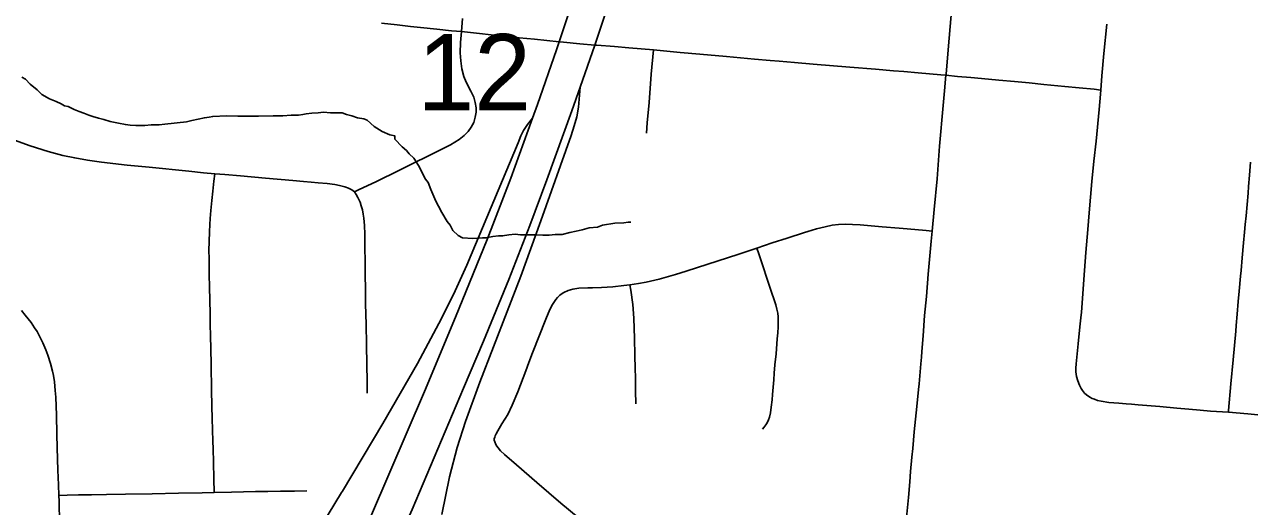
# Model space of a CAD drawing. Extents: x 0 to 34, y 0 to 22.
# Drawn here: x 3.895 to 4.566, y 15.8 to 16.064 of the extents above; entities that cross this region are included whole.
import ezdxf

# ---------------------------------------------------------------- set-up
doc = ezdxf.new("R2010")
doc.units = 0
for name, color, linetype in [('GM_X_City_Street', 7, 'Continuous'), ('GM_X_Interchange_Ramps', 7, 'Continuous'), ('GM_X_Interstate_Route', 7, 'Continuous'), ('GM_X_Minor_River', 7, 'Continuous'), ('GM_X_Section_Text', 7, 'Continuous')]:
    doc.layers.add(name, color=color, linetype=linetype)

msp = doc.modelspace()

# ---------------------------------------------------------------- linework, layer by layer
at = {"layer": 'GM_X_City_Street'}
for points in [[(4.37821, 15.79422), (4.37887, 15.80158), (4.37925, 15.80522), (4.37997, 15.81377), (4.3804, 15.81948), (4.38112, 15.82726), (4.38154, 15.83215), (4.38229, 15.84127), (4.38376, 15.85511), (4.38476, 15.86441), (4.38503, 15.86745), (4.38596, 15.87848), (4.38628, 15.88214), (4.38652, 15.88517), (4.38721, 15.89379), (4.38805, 15.90493), (4.38908, 15.91542), (4.39009, 15.92753), (4.39118, 15.93957), (4.39169, 15.94576), (4.39219, 15.95124), (4.39327, 15.96304), (4.39486, 15.97977), (4.39628, 15.99774), (4.39829, 16.01999), (4.399, 16.02798), (4.39973, 16.0366), (4.39978, 16.03725), (4.40112, 16.05272), (4.40372, 16.08242)], [(4.1351, 16.06761), (4.13448, 16.06049), (4.13398, 16.0546), (4.13376, 16.04894), (4.13402, 16.04452), (4.13469, 16.04013), (4.13581, 16.03581), (4.13699, 16.03282), (4.13962, 16.02785), (4.14114, 16.02457), (4.14198, 16.02173), (4.14243, 16.01881), (4.14246, 16.01645), (4.14204, 16.01353), (4.14116, 16.01072), (4.13983, 16.00809), (4.13809, 16.00571), (4.13598, 16.00361), (4.13312, 16.0014), (4.12842, 15.99855), (4.11575, 15.99204), (4.10849, 15.98855), (4.10015, 15.98439), (4.08791, 15.97837), (4.07813, 15.97374), (4.07581, 15.97263)], [(4.09061, 16.06506), (4.09933, 16.06412), (4.10659, 16.06329), (4.11203, 16.06269), (4.12091, 16.06175), (4.12908, 16.06092), (4.13448, 16.06049), (4.14104, 16.05974), (4.15401, 16.05841), (4.16601, 16.05716), (4.17438, 16.05631), (4.18798, 16.05489), (4.19027, 16.05466), (4.19919, 16.05379), (4.2074, 16.05313), (4.20866, 16.05303), (4.21834, 16.05227), (4.22606, 16.05161), (4.23955, 16.05042), (4.25413, 16.04912), (4.2649, 16.04813), (4.27959, 16.04683), (4.29492, 16.04541), (4.30341, 16.04465), (4.30841, 16.04422), (4.31679, 16.04357), (4.32712, 16.0427), (4.34714, 16.04095), (4.36117, 16.03986), (4.37107, 16.03899), (4.37673, 16.03856), (4.38456, 16.03789), (4.39686, 16.03684), (4.39973, 16.0366), (4.40599, 16.03595), (4.41328, 16.0353), (4.41915, 16.03476), (4.42873, 16.03389), (4.43722, 16.03312), (4.44537, 16.03236), (4.45342, 16.0316), (4.46484, 16.03051), (4.47268, 16.02975), (4.48094, 16.02888), (4.48455, 16.0285)], [(4.47976, 15.85954), (4.47847, 15.86023), (4.47678, 15.86142), (4.4757, 15.86241), (4.4745, 15.8639), (4.47381, 15.86504), (4.47287, 15.86675), (4.47191, 15.86912), (4.47125, 15.87157), (4.47092, 15.87408), (4.47082, 15.87617), (4.47101, 15.87845), (4.47137, 15.8821), (4.47217, 15.88949), (4.47309, 15.89872), (4.47357, 15.90365), (4.47388, 15.90673), (4.47434, 15.91164), (4.47527, 15.92462), (4.47639, 15.93956), (4.47748, 15.95216), (4.47818, 15.96118), (4.47966, 15.97844), (4.48075, 15.98954), (4.48194, 16.00044), (4.48364, 16.01782), (4.48405, 16.02199), (4.48455, 16.0285), (4.48514, 16.03618), (4.48615, 16.04856), (4.48779, 16.06451)], [(4.23569, 16.00489), (4.23622, 16.0105), (4.23715, 16.02173), (4.23825, 16.03725), (4.23955, 16.05042)], [(3.88778, 16.0018), (3.89824, 15.99792), (3.90806, 15.99478), (3.91613, 15.99265), (3.92269, 15.99128), (3.92971, 15.99006), (3.93743, 15.98891), (3.95149, 15.98737), (3.96341, 15.98625), (3.98514, 15.98401), (3.99315, 15.98315), (3.99944, 15.9826), (4.00487, 15.98212), (4.01352, 15.98141), (4.02707, 15.98024), (4.04204, 15.97888), (4.04795, 15.97837), (4.05207, 15.97803), (4.05604, 15.97769), (4.061, 15.9772), (4.06505, 15.97665), (4.06776, 15.97614), (4.0705, 15.97545), (4.07256, 15.97476), (4.07445, 15.97374), (4.07581, 15.97263), (4.07685, 15.97133), (4.07779, 15.96962), (4.07891, 15.96713), (4.07959, 15.96499), (4.08019, 15.96285), (4.0807, 15.96053), (4.08105, 15.95822), (4.08138, 15.95428), (4.08156, 15.94947), (4.08156, 15.94235), (4.08165, 15.93438), (4.08174, 15.92658), (4.08182, 15.92006), (4.08199, 15.9114), (4.08229, 15.89997), (4.08244, 15.889), (4.0826, 15.87802), (4.08275, 15.86902), (4.08275, 15.86247)], [(4.55447, 15.85197), (4.55454, 15.85288), (4.55579, 15.86755), (4.55701, 15.88067), (4.55767, 15.88844), (4.55842, 15.89641), (4.55865, 15.8995), (4.55918, 15.90564), (4.55979, 15.91272), (4.5603, 15.91831), (4.5611, 15.92653), (4.56143, 15.92958), (4.56199, 15.93662), (4.56276, 15.94476), (4.56327, 15.9507), (4.56366, 15.95473), (4.56407, 15.95965), (4.56517, 15.97197), (4.56542, 15.97564), (4.56589, 15.9818), (4.56657, 15.98901)], [(3.99904, 15.80802), (3.99893, 15.81551), (3.9987, 15.82457), (3.99848, 15.83184), (3.99837, 15.83609), (3.99803, 15.84849), (3.99781, 15.85521), (3.99761, 15.8643), (3.99736, 15.87779), (3.99714, 15.88707), (3.99701, 15.89344), (3.99684, 15.90042), (3.9968, 15.90641), (3.99669, 15.91289), (3.99647, 15.92106), (3.99638, 15.92689), (3.99633, 15.93129), (3.99624, 15.93616), (3.9962, 15.94049), (3.99624, 15.94543), (3.99647, 15.9508), (3.99669, 15.95482), (3.99691, 15.95817), (3.99725, 15.96253), (3.99781, 15.9679), (3.9983, 15.97313), (3.99891, 15.97862), (3.99944, 15.9826)], [(4.15237, 15.83663), (4.15245, 15.83747), (4.15267, 15.83835), (4.15291, 15.83911), (4.15338, 15.84016), (4.15433, 15.84176), (4.15662, 15.84552), (4.15977, 15.8508), (4.16217, 15.85576), (4.16525, 15.86309), (4.16963, 15.87464), (4.17136, 15.87928), (4.17333, 15.8845), (4.1806, 15.90303), (4.18283, 15.90821), (4.18428, 15.91106), (4.18609, 15.91374), (4.18708, 15.91483), (4.18839, 15.91605), (4.18959, 15.91693), (4.19057, 15.91753), (4.19295, 15.91866), (4.19545, 15.91945), (4.19864, 15.91995), (4.20369, 15.92016), (4.20616, 15.9202), (4.21112, 15.92031), (4.21727, 15.92061), (4.2234, 15.92135), (4.22671, 15.92185), (4.23133, 15.92256), (4.23556, 15.9233), (4.23795, 15.9238), (4.24273, 15.9249), (4.25172, 15.92742), (4.25742, 15.92933), (4.28637, 15.93864), (4.29618, 15.94191), (4.30462, 15.94473), (4.31289, 15.9474), (4.32232, 15.95041), (4.32408, 15.95096), (4.32881, 15.95238), (4.33365, 15.95359), (4.33738, 15.95438), (4.34096, 15.9548), (4.34455, 15.95495), (4.34849, 15.95488), (4.35286, 15.95459), (4.36479, 15.9536), (4.37408, 15.9528), (4.37845, 15.95237), (4.38892, 15.95151), (4.39219, 15.95124)], [(4.29926, 15.84275), (4.30009, 15.84367), (4.3012, 15.84513), (4.30186, 15.84616), (4.30264, 15.84782), (4.30319, 15.84922), (4.30369, 15.85159), (4.30412, 15.85474), (4.30455, 15.85868), (4.30476, 15.86177), (4.30541, 15.86979), (4.3057, 15.87331), (4.30612, 15.87797), (4.3067, 15.88391), (4.30739, 15.89219), (4.3077, 15.89545), (4.30785, 15.89883), (4.30792, 15.90155), (4.30793, 15.90428), (4.30767, 15.90625), (4.30713, 15.90836), (4.30652, 15.91084), (4.30548, 15.91402), (4.30442, 15.91715), (4.30182, 15.92484), (4.29953, 15.93216), (4.29724, 15.93882), (4.29618, 15.94191)], [(4.22993, 15.85648), (4.2299, 15.8577), (4.22983, 15.86266), (4.22975, 15.86661), (4.22967, 15.87098), (4.2295, 15.87577), (4.22941, 15.88316), (4.2292, 15.89234), (4.22883, 15.90352), (4.22827, 15.91095), (4.22714, 15.9189), (4.22671, 15.92185)], [(3.89351, 15.90761), (3.89562, 15.90511), (3.89726, 15.90311), (3.8988, 15.90106), (3.90074, 15.89828), (3.90205, 15.89617), (3.90347, 15.89361), (3.90524, 15.88991), (3.90683, 15.88615), (3.90791, 15.8833), (3.90945, 15.87864), (3.91053, 15.87454), (3.91104, 15.87209), (3.91155, 15.86868), (3.91183, 15.86629), (3.91206, 15.86378), (3.91229, 15.86019), (3.91263, 15.85035), (3.91297, 15.83993), (3.91309, 15.83242), (3.91349, 15.8203), (3.91383, 15.81216), (3.91405, 15.8063), (3.91417, 15.80322), (3.91439, 15.79127)], [(4.47976, 15.85954), (4.48115, 15.85904), (4.48274, 15.85847), (4.48465, 15.85803), (4.48898, 15.85736), (4.49444, 15.85686), (4.49835, 15.85661), (4.5014, 15.85634), (4.50507, 15.85606), (4.51695, 15.85507), (4.52608, 15.85418), (4.53281, 15.85359), (4.53893, 15.85303), (4.5446, 15.85258), (4.55447, 15.85197), (4.56497, 15.85109), (4.57052, 15.85062)], [(4.15237, 15.83663), (4.15271, 15.83571), (4.15329, 15.83428), (4.15384, 15.83332), (4.15447, 15.83244), (4.15586, 15.83078), (4.15797, 15.82887), (4.16452, 15.82317), (4.17578, 15.81348), (4.18886, 15.80208), (4.1983, 15.79435)], [(3.91405, 15.8063), (3.91854, 15.80646), (3.9248, 15.80668), (3.93195, 15.80679), (3.94008, 15.80692), (3.95051, 15.80702), (3.96516, 15.80724), (3.97958, 15.80758), (3.99244, 15.8078), (3.99904, 15.80802), (4.00854, 15.80825), (4.02173, 15.80847), (4.02844, 15.80858), (4.03538, 15.8087), (4.04309, 15.80881), (4.0498, 15.80892)]]:
    msp.add_lwpolyline(points, dxfattribs=at)
at = {"layer": 'GM_X_Interchange_Ramps'}
for points in [[(4.12365, 15.79586), (4.12798, 15.81651), (4.13218, 15.83273), (4.13665, 15.84694), (4.14452, 15.86852), (4.16688, 15.92645), (4.17788, 15.9568), (4.19454, 16.00366), (4.19611, 16.00889), (4.19756, 16.01381), (4.19857, 16.01902), (4.19942, 16.03008)], [(4.17334, 16.01314), (4.17055, 16.00965), (4.16847, 16.00629), (4.16702, 16.00339), (4.16556, 15.99963), (4.13747, 15.93253), (4.13104, 15.91839), (4.12355, 15.90336), (4.11034, 15.8787), (4.09145, 15.84581), (4.06926, 15.80881)], [(4.06926, 15.80881), (4.06875, 15.80795), (4.05358, 15.78298), (4.0351, 15.75205), (4.01147, 15.71046), (4.00147, 15.69185), (3.98862, 15.66693), (3.98806, 15.66545), (3.98659, 15.66157), (3.98573, 15.65749)]]:
    msp.add_lwpolyline(points, dxfattribs=at)
at = {"layer": 'GM_X_Interstate_Route'}
for points in [[(4.04209, 15.6451), (4.04357, 15.64893), (4.04429, 15.65077), (4.04711, 15.65808), (4.05031, 15.66635), (4.0632, 15.69737), (4.08832, 15.7549), (4.09895, 15.77929), (4.10742, 15.79874), (4.13553, 15.86511), (4.14651, 15.89081), (4.16048, 15.92466), (4.17191, 15.95418), (4.18122, 15.9792), (4.19495, 16.01715), (4.19942, 16.03008), (4.2074, 16.05313), (4.21119, 16.0641), (4.21847, 16.08652)], [(3.93014, 15.35354), (3.94101, 15.39627), (3.95006, 15.42983), (3.95887, 15.46023), (3.97267, 15.50405), (3.98526, 15.54173), (4.00587, 15.59967), (4.02014, 15.63941), (4.02545, 15.65322), (4.0282, 15.66039), (4.0326, 15.67184), (4.04557, 15.70341), (4.05882, 15.73421), (4.07579, 15.7736), (4.1142, 15.86326), (4.13123, 15.90398), (4.1485, 15.94663), (4.16145, 15.98029), (4.17334, 16.01314), (4.17605, 16.02063), (4.18654, 16.05056), (4.18798, 16.05489), (4.19729, 16.08303)]]:
    msp.add_lwpolyline(points, dxfattribs=at)
at = {"layer": 'GM_X_Minor_River'}
for points in [[(3.89377, 16.03561), (3.89565, 16.03445), (3.89828, 16.03176), (3.90205, 16.02868), (3.90468, 16.026), (3.90883, 16.02367), (3.91261, 16.02212), (3.91525, 16.02095), (3.91714, 16.01979), (3.91903, 16.01939), (3.92243, 16.01783), (3.92508, 16.01667), (3.92773, 16.01588), (3.93037, 16.01471), (3.93264, 16.01393), (3.93567, 16.01314), (3.9387, 16.01235), (3.9421, 16.01117), (3.94664, 16.01036), (3.95043, 16.00956), (3.95308, 16.00916), (3.95611, 16.00913), (3.95877, 16.0091), (3.96104, 16.00907), (3.96446, 16.00942), (3.96901, 16.00937), (3.97205, 16.00972), (3.98382, 16.01112), (3.98686, 16.01185), (3.99028, 16.01257), (3.9937, 16.0133), (3.99636, 16.01365), (3.99826, 16.01401), (4.00585, 16.01431), (4.01192, 16.01425), (4.01685, 16.0142), (4.0195, 16.01417), (4.0233, 16.01413), (4.03126, 16.01443), (4.03657, 16.01437), (4.04113, 16.01471), (4.0453, 16.01466), (4.04758, 16.01502), (4.04948, 16.01538), (4.05251, 16.01573), (4.05593, 16.01607), (4.05897, 16.01642), (4.06276, 16.016), (4.06617, 16.01596), (4.06921, 16.01593), (4.07148, 16.01515), (4.0745, 16.01436), (4.07753, 16.01319), (4.08094, 16.01277), (4.08283, 16.01199), (4.08659, 16.00853), (4.09112, 16.00583), (4.09527, 16.00388), (4.09792, 16.00347), (4.09791, 16.00157), (4.10204, 15.99735)], [(4.10204, 15.99735), (4.1043, 15.99543), (4.1058, 15.99351), (4.10843, 15.99121), (4.10993, 15.98853), (4.11142, 15.98623), (4.11291, 15.98318), (4.11478, 15.97974), (4.11628, 15.97782), (4.11776, 15.97401), (4.11925, 15.97019), (4.12036, 15.96752), (4.12185, 15.96484), (4.12372, 15.9614), (4.12671, 15.95643), (4.12821, 15.95452), (4.1297, 15.95146), (4.13271, 15.94877), (4.13498, 15.9476), (4.14066, 15.94717), (4.14597, 15.94749), (4.14787, 15.94747), (4.15167, 15.94819), (4.15471, 15.94854), (4.15698, 15.94852), (4.1604, 15.94924), (4.16382, 15.94959), (4.16685, 15.94917), (4.17102, 15.94913), (4.1752, 15.94909), (4.17899, 15.94905), (4.1824, 15.94901), (4.18582, 15.94936), (4.18961, 15.94932), (4.19379, 15.95042), (4.19721, 15.95114), (4.20063, 15.95186), (4.20444, 15.95296), (4.20899, 15.9533), (4.21166, 15.95441), (4.21393, 15.95477), (4.21621, 15.95512), (4.21849, 15.95548), (4.22343, 15.95581), (4.2257, 15.95616), (4.22722, 15.95615)]]:
    msp.add_lwpolyline(points, dxfattribs=at)

# ---------------------------------------------------------------- texts
at = {"layer": 'GM_X_Section_Text'}
msp.add_text('12', height=0.041856, rotation=0.00001, dxfattribs=at).set_placement((4.11031, 16.01728))

doc.saveas('drawing.dxf')
